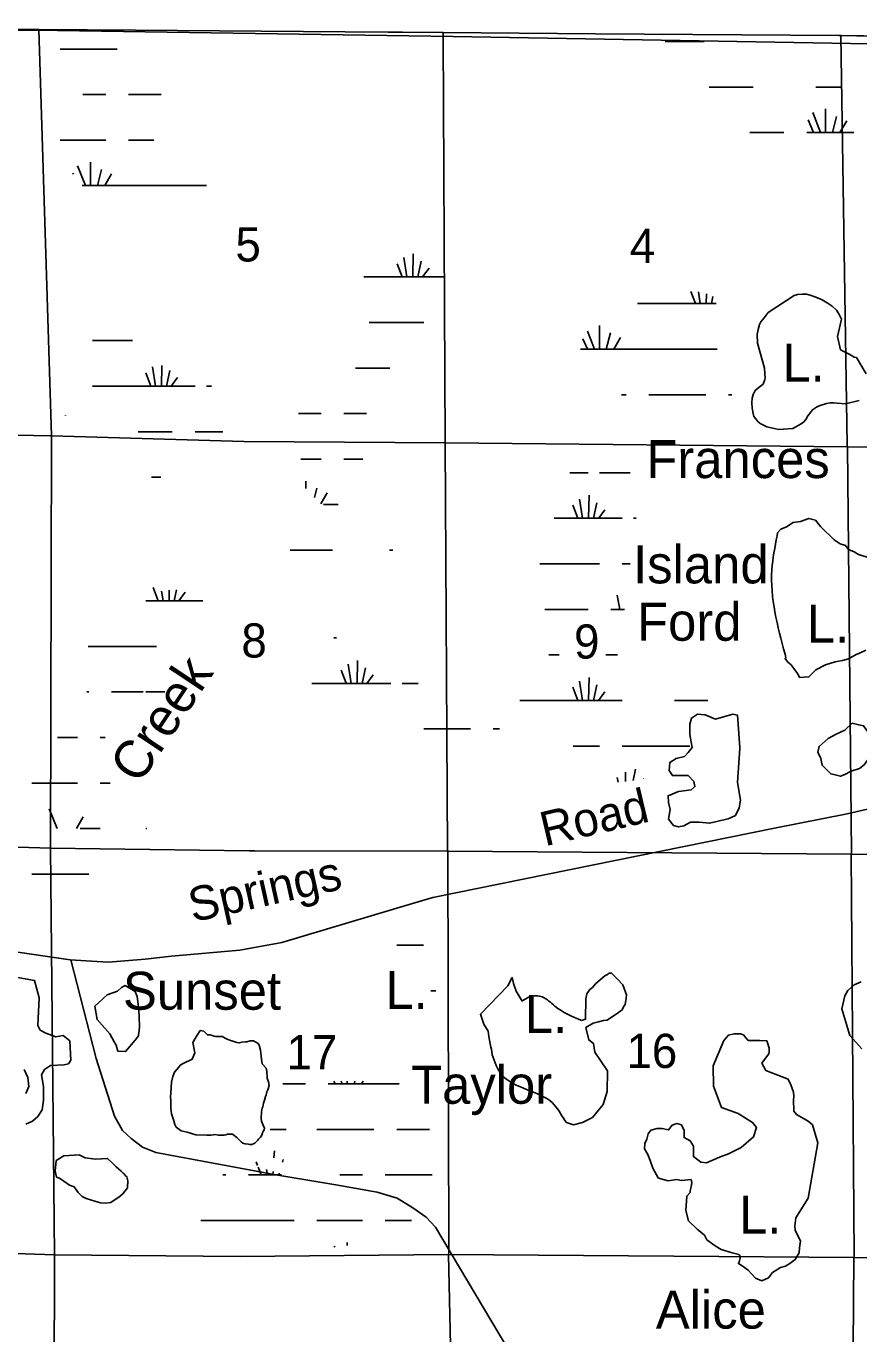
# Model space of a CAD drawing. Extents: x 380424 to 701066, y 1117407 to 1412949.
# Drawn here: x 451978 to 462944, y 1379088 to 1396314 of the extents above; entities that cross this region are included whole.
import ezdxf

# ---------------------------------------------------------------- set-up
doc = ezdxf.new("R2010")
doc.units = 0
for name, color, linetype in [('County Boundary', 7, 'Continuous'), ('Lakes and Ponds', 7, 'Continuous'), ('Lakes and Ponds Text', 7, 'Continuous'), ('Local Roads Paved', 7, 'Continuous'), ('Local Roads Related Text', 7, 'Continuous'), ('Narrow River Creek and Branch and Slough Text', 7, 'Continuous'), ('Section Lines', 7, 'Continuous'), ('Section Numbers', 7, 'Continuous'), ('Swamps', 7, 'Continuous'), ('Township  and Range lines', 7, 'Continuous')]:
    doc.layers.add(name, color=color, linetype=linetype)

msp = doc.modelspace()

# ---------------------------------------------------------------- linework, layer by layer
at = {"layer": 'County Boundary'}
msp.add_lwpolyline([(444709, 1396293), (446440, 1396285), (452102, 1396261), (457598, 1396176), (465384, 1396044), (465655, 1396044), (481571, 1395878), (501713, 1395620), (510342, 1395422), (515666, 1395275), (520926, 1395193), (525511, 1395188), (531177, 1395181), (531365, 1395181), (536977, 1395158), (542179, 1395155), (542521, 1395155), (587352, 1395146), (594829, 1395183), (611544, 1395147), (638076, 1395204)], dxfattribs=at)
at = {"layer": 'Lakes and Ponds'}
for points in [[(462946, 1391384), (462766, 1391337), (462659, 1391348), (462613, 1391354), (462566, 1391352), (462519, 1391344), (462422, 1391314), (462388, 1391297), (462335, 1391259), (462305, 1391223), (462271, 1391180), (462244, 1391131), (462214, 1391097), (462186, 1391076), (462076, 1391015), (461891, 1391000), (461734, 1391034), (461645, 1391078), (461615, 1391106), (461586, 1391140), (461560, 1391174), (461550, 1391210), (461537, 1391280), (461535, 1391354), (461539, 1391414), (461550, 1391464), (461579, 1391513), (461632, 1391560), (461683, 1391600), (461705, 1391658), (461709, 1391675), (461707, 1391738), (461702, 1391806), (461700, 1391810), (461611, 1392139), (461607, 1392177), (461603, 1392218), (461603, 1392252), (461618, 1392317), (461637, 1392383), (461652, 1392419), (461696, 1392474), (461749, 1392542), (462093, 1392765), (462137, 1392778), (462197, 1392784), (462254, 1392782), (462301, 1392769), (462377, 1392744), (462460, 1392710), (462526, 1392670), (462594, 1392625), (462649, 1392574), (462679, 1392523), (462715, 1392455), (462664, 1392227), (462703, 1392052), (462825, 1391988), (462884, 1391955), (462912, 1391948), (463041, 1391732)], [(463187, 1389279), (462941, 1389355), (462882, 1389390), (462809, 1389418), (462768, 1389474), (462699, 1389495), (462617, 1389546), (462440, 1389722), (462371, 1389807), (462286, 1389830), (462175, 1389791), (462079, 1389775), (461990, 1389717), (461916, 1389686), (461874, 1389638), (461868, 1389602)], [(461972, 1388042), (461982, 1387994), (461973, 1387985), (462010, 1387936), (462052, 1387902), (462110, 1387824), (462138, 1387784), (462164, 1387736), (462286, 1387741), (462375, 1387837), (462504, 1387899), (462631, 1387939), (462729, 1387959), (462808, 1387980), (462919, 1388043), (462935, 1388048), (463035, 1388094)], [(451975, 1381851), (452062, 1381890), (452133, 1381953), (452188, 1382040), (452204, 1382166), (452204, 1382348), (452180, 1382498), (452220, 1382569), (452298, 1382624), (452480, 1382632), (452535, 1382647), (452566, 1382695), (452551, 1382947), (452464, 1383018), (452369, 1383002), (452235, 1383050), (452164, 1383089), (452133, 1383152), (452149, 1383515), (452086, 1383744), (451299, 1383885)], [(458115, 1382765), (458106, 1382838), (458097, 1382865), (458087, 1382910), (458072, 1383007), (458061, 1383076), (458006, 1383168), (457961, 1383299), (458320, 1383674), (458362, 1383745), (458370, 1383773), (458378, 1383784), (458394, 1383704), (458431, 1383603), (458510, 1383471)], [(459289, 1383218), (459345, 1383232), (459350, 1383503), (459361, 1383565), (459403, 1383623), (459435, 1383650), (459477, 1383697), (459572, 1383782), (459599, 1383803), (459635, 1383824), (459657, 1383840), (459688, 1383840), (459766, 1383761), (459834, 1383684), (459885, 1383556), (459879, 1383509), (459865, 1383426), (459846, 1383395), (459825, 1383358), (459761, 1383308), (459671, 1383250), (459629, 1383222), (459580, 1383218), (459517, 1383200), (459445, 1383182), (459350, 1383123), (459386, 1382960), (459449, 1382915), (459467, 1382797), (459635, 1382553), (459630, 1382281), (459576, 1382109), (459436, 1381937), (459304, 1381874), (459187, 1381842), (459092, 1381874), (459070, 1381898)], [(462981, 1382844), (462827, 1383019), (462719, 1383368), (462759, 1383543), (462800, 1383610), (462880, 1383684), (462974, 1383724)], [(451951, 1382569), (451999, 1382466), (452015, 1382348), (451975, 1382253)]]:
    msp.add_lwpolyline(points, dxfattribs=at)
for points in [[(461375, 1386803), (461347, 1386349), (461383, 1386118), (461368, 1386017), (461318, 1385916), (461224, 1385873), (460979, 1385815), (460842, 1385830), (460727, 1385830), (460640, 1385779), (460568, 1385765), (460503, 1385786), (460438, 1385866), (460460, 1385996), (460438, 1386089), (460431, 1386176), (460568, 1386234), (460734, 1386255), (460784, 1386298), (460770, 1386363), (460698, 1386443), (460489, 1386443), (460446, 1386508), (460453, 1386616), (460539, 1386666), (460647, 1386695), (460698, 1386745), (460748, 1386810), (460720, 1386983), (460720, 1387120), (460741, 1387200), (460820, 1387250), (460921, 1387243), (461058, 1387185), (461282, 1387250), (461347, 1387236), (461375, 1386810)], [(463128, 1386874), (463133, 1386926), (463073, 1387001), (463006, 1387099), (462942, 1387109), (462855, 1387131), (462760, 1387042), (462643, 1386988), (462541, 1386931), (462421, 1386827), (462405, 1386752), (462443, 1386665), (462460, 1386579), (462507, 1386532), (462573, 1386463), (462630, 1386450), (462700, 1386434), (462760, 1386457), (462843, 1386499), (462954, 1386536), (463012, 1386583), (463059, 1386647), (463117, 1386752)], [(453462, 1383360), (453441, 1383534), (453411, 1383597), (453282, 1383675), (453232, 1383652), (453179, 1383601), (453045, 1383553), (452882, 1383403), (452912, 1383228), (453079, 1383039), (453105, 1382991), (453133, 1382945), (453165, 1382892), (453183, 1382812), (453287, 1382807), (453413, 1382957), (453455, 1383014), (453455, 1383033), (453466, 1383077), (453469, 1383146), (453466, 1383251)], [(454670, 1382954), (454617, 1382974), (454560, 1383004), (454522, 1383004), (454502, 1383004), (454473, 1383006), (454453, 1383009), (454401, 1383025), (454364, 1383026), (454317, 1383076), (454270, 1383083), (454228, 1383024), (454173, 1382925), (454198, 1382791), (454164, 1382706), (454045, 1382651), (454008, 1382628), (453988, 1382603), (453932, 1382534), (453909, 1382477), (453891, 1382405), (453887, 1382338), (453884, 1382254), (453879, 1382212), (453882, 1382163), (453884, 1382113), (453882, 1382061), (453891, 1381985), (453906, 1381945), (453921, 1381896), (453936, 1381844), (453953, 1381811), (454020, 1381764), (454100, 1381744), (454210, 1381712), (454359, 1381705), (454413, 1381705), (454468, 1381713), (454508, 1381705), (454584, 1381705), (454609, 1381712), (454631, 1381719), (454693, 1381717), (454752, 1381675), (454807, 1381618), (454829, 1381601), (454862, 1381593), (454905, 1381586), (454923, 1381581), (454950, 1381584), (454990, 1381599), (455027, 1381641), (455039, 1381651), (455064, 1381680), (455081, 1381707), (455092, 1381737), (455098, 1381754), (455113, 1381774), (455118, 1381799), (455096, 1381844), (455076, 1381891), (455071, 1381930), (455071, 1381962), (455077, 1381988), (455077, 1382015), (455084, 1382060), (455094, 1382080), (455104, 1382128), (455118, 1382165), (455130, 1382213), (455133, 1382222), (455138, 1382237), (455143, 1382254), (455145, 1382276), (455160, 1382301), (455178, 1382359), (455170, 1382410), (455150, 1382455), (455150, 1382465), (455145, 1382544), (455138, 1382587), (455086, 1382645), (455079, 1382707), (455064, 1382826), (455048, 1382891), (455033, 1382911), (454970, 1382949), (454928, 1382947), (454882, 1382933), (454865, 1382935), (454820, 1382930), (454783, 1382920), (454750, 1382927), (454714, 1382938), (454685, 1382948)], [(462086, 1382020), (462084, 1382171), (462087, 1382215), (462082, 1382273), (462048, 1382369), (462015, 1382445), (461718, 1382557), (461668, 1382654), (461754, 1382771), (461764, 1382790), (461764, 1382852), (461743, 1382910), (461732, 1382947), (461634, 1382953), (461637, 1382953), (461485, 1382953), (461454, 1382989), (461429, 1383024), (461388, 1383039), (461353, 1383039), (461302, 1383039), (461226, 1383024), (461165, 1382953), (461023, 1382618), (461028, 1382349), (461134, 1382069), (461353, 1381993), (461544, 1381874), (461595, 1381808), (461556, 1381683), (461393, 1381541), (461226, 1381460), (461109, 1381414), (460936, 1381343), (460863, 1381351), (460764, 1381424), (460764, 1381561), (460723, 1381632), (460642, 1381673), (460642, 1381765), (460606, 1381841), (460545, 1381861), (460484, 1381836), (460439, 1381775), (460352, 1381795), (460288, 1381795), (460205, 1381770), (460169, 1381724), (460152, 1381652), (460124, 1381597), (460119, 1381526), (460164, 1381450), (460196, 1381372), (460229, 1381271), (460300, 1381142), (460337, 1381132), (460431, 1381103), (460544, 1381120), (460606, 1381109), (460734, 1381120), (460745, 1381083), (460739, 1381052), (460729, 1381009), (460723, 1380972), (460723, 1380951), (460677, 1380902), (460666, 1380711), (460700, 1380576), (460814, 1380469), (460911, 1380386), (460943, 1380328), (461053, 1380246), (461129, 1380200), (461277, 1380154), (461363, 1380134), (461385, 1380106), (461370, 1380050), (461358, 1380014), (461405, 1379984), (461486, 1379927), (461582, 1379820), (461667, 1379785), (461753, 1379824), (461806, 1379895), (461913, 1379963), (461979, 1379982), (462033, 1380016), (462104, 1380068), (462157, 1380154), (462162, 1380223), (462175, 1380312), (462104, 1380449), (462102, 1380513), (462112, 1380618), (462277, 1380876), (462405, 1381603), (462333, 1381841), (462277, 1381892), (462191, 1381937), (462123, 1381977)], [(452891, 1381391), (453050, 1381400), (453118, 1381332), (453161, 1381288), (453200, 1381256), (453227, 1381231), (453257, 1381206), (453271, 1381191), (453283, 1381174), (453302, 1381157), (453317, 1381106), (453313, 1381011), (453249, 1380933), (453200, 1380890), (453152, 1380856), (453092, 1380819), (453028, 1380809), (452955, 1380812), (452882, 1380834), (452768, 1380870), (452715, 1380897), (452662, 1380948), (452611, 1381026), (452550, 1381045), (452472, 1381098), (452416, 1381140), (452378, 1381154), (452368, 1381191), (452358, 1381234), (452375, 1381370), (452475, 1381431), (452676, 1381446), (452754, 1381409)]]:
    msp.add_lwpolyline(points, close=True, dxfattribs=at)
for points in [[(461868, 1389602), (461798, 1389153), (461972, 1388042)], [(458510, 1383471), (458608, 1383526), (458775, 1383526), (458941, 1383404), (459289, 1383218)], [(459070, 1381898), (458908, 1382130), (458243, 1382499), (458115, 1382765)]]:
    msp.add_spline(points, degree=3, dxfattribs=at)
at = {"layer": 'Local Roads Paved'}
for points in [[(469461, 1387536), (466024, 1387550), (465889, 1387546), (465789, 1387515), (465684, 1387465), (465349, 1387171), (464894, 1386801), (464508, 1386558), (464145, 1386328), (463823, 1386194), (463609, 1386127), (462790, 1385939), (461833, 1385748), (457335, 1384838), (457067, 1384758), (455344, 1384242), (454790, 1384144), (453892, 1384064), (453543, 1384023), (453060, 1383983), (452838, 1383997), (452557, 1384017), (451087, 1384231)], [(452565, 1384016), (452899, 1382714), (453140, 1381956), (453247, 1381768), (453362, 1381660), (453509, 1381546), (453684, 1381479), (455294, 1381178), (456058, 1381050), (456602, 1380956), (456863, 1380876), (457071, 1380748), (457246, 1380627), (457367, 1380493), (458316, 1378899)]]:
    msp.add_lwpolyline(points, dxfattribs=at)
at = {"layer": 'Section Lines'}
for points in [[(452145, 1396270), (452145, 1396270), (452310, 1390916), (452298, 1390916), (446467, 1391031), (446457, 1391031), (446390, 1394947), (446378, 1395736), (446371, 1396147), (446364, 1396314), (446370, 1396314), (446372, 1396314), (446837, 1396310), (452144, 1396270)], [(457468, 1396229), (457468, 1396229), (457468, 1396163), (457497, 1390841), (457495, 1390825), (454844, 1390842), (452310, 1390916), (452145, 1396270), (452145, 1396270), (453416, 1396260), (453416, 1396260), (456177, 1396239), (456179, 1396239), (456744, 1396234), (456936, 1396233), (457452, 1396229), (457452, 1396229)], [(462708, 1396189), (462788, 1390793), (462795, 1390773), (457495, 1390825), (457497, 1390841), (457468, 1396163), (457468, 1396229), (457468, 1396229), (459476, 1396214), (462681, 1396189)], [(467981, 1396111), (467981, 1396111), (468137, 1390729), (462795, 1390773), (462788, 1390793), (462708, 1396189), (462711, 1396189), (464812, 1396158), (464993, 1396155), (466037, 1396140), (467582, 1396117)], [(452310, 1390916), (452299, 1385488), (446615, 1385661), (446601, 1385661), (446601, 1385678), (446495, 1389346), (446475, 1390128), (446467, 1390421), (446460, 1390858), (446457, 1391031), (446467, 1391031), (452298, 1390916)], [(457495, 1390825), (457526, 1385461), (457529, 1385445), (454991, 1385449), (454915, 1385450), (452299, 1385488), (452310, 1390916), (454844, 1390842)], [(462795, 1390773), (462847, 1385421), (462842, 1385405), (457529, 1385445), (457526, 1385461), (457495, 1390825)], [(468137, 1390729), (468136, 1385356), (462842, 1385405), (462847, 1385421), (462795, 1390773)], [(452299, 1385488), (452350, 1380129), (446680, 1380322), (446680, 1380322), (446680, 1380323), (446680, 1380324), (446601, 1385661), (446615, 1385661)], [(457529, 1385445), (457546, 1380158), (457541, 1380133), (454794, 1380109), (452350, 1380129), (452299, 1385488), (454915, 1385450), (454991, 1385449)], [(462842, 1385405), (462880, 1380113), (462877, 1380092), (457541, 1380133), (457546, 1380158), (457529, 1385445)], [(468136, 1385356), (468132, 1380031), (468135, 1380016), (462877, 1380092), (462880, 1380113), (462842, 1385405)], [(452350, 1380129), (452338, 1374951), (446760, 1374945), (446760, 1374945), (446680, 1380322), (446680, 1380322)], [(457541, 1380133), (457653, 1374938), (454750, 1374954), (452338, 1374951), (452350, 1380129), (454794, 1380109)], [(462877, 1380092), (462839, 1374767), (462831, 1374772), (457653, 1374938), (457541, 1380133)], [(468135, 1380016), (468109, 1374719), (462839, 1374767), (462877, 1380092)]]:
    msp.add_lwpolyline(points, close=True, dxfattribs=at)
at = {"layer": 'Swamps'}
for p, q in [((452425, 1396013), (453175, 1396013)), ((452725, 1395413), (453025, 1395413)), ((462337, 1395175), (462440, 1394912)), ((462506, 1395223), (462506, 1394912)), ((462651, 1395126), (462597, 1394912)), ((462276, 1395078), (462347, 1394912)), ((462784, 1395066), (462694, 1394912)), ((452425, 1394813), (453025, 1394813)), ((453325, 1394813), (453660, 1394813)), ((461507, 1394912), (461957, 1394912)), ((452824, 1394524), (452824, 1394213)), ((452969, 1394427), (452915, 1394213)), ((453102, 1394367), (453012, 1394213)), ((456991, 1393011), (456952, 1393265)), ((457069, 1393011), (457075, 1393315)), ((457137, 1393011), (457179, 1393217)), ((456929, 1393012), (456863, 1393185)), ((457199, 1393011), (457283, 1393124)), ((460028, 1392659), (460628, 1392659)), ((456763, 1392411), (457213, 1392411)), ((459527, 1392370), (459527, 1392059)), ((459672, 1392273), (459618, 1392059)), ((459805, 1392213), (459715, 1392059)), ((460628, 1392059), (461078, 1392059)), ((453618, 1391573), (453552, 1391746)), ((453680, 1391572), (453641, 1391825)), ((453825, 1391572), (453868, 1391778)), ((453887, 1391571), (453971, 1391685)), ((456313, 1391811), (456763, 1391811)), ((452852, 1391572), (453452, 1391572)), ((453452, 1391572), (454202, 1391572)), ((460178, 1391459), (460628, 1391459)), ((460628, 1391459), (460928, 1391459)), ((455563, 1391211), (455863, 1391211)), ((453452, 1390972), (453902, 1390972)), ((455807, 1390226), (455777, 1390106)), ((455940, 1390165), (455857, 1390023)), ((459384, 1389831), (459390, 1390134)), ((459244, 1389832), (459178, 1390005)), ((459306, 1389831), (459267, 1390084)), ((459451, 1389831), (459494, 1390036)), ((459514, 1389830), (459597, 1389944)), ((459078, 1389831), (459828, 1389831)), ((455455, 1389411), (456013, 1389411)), ((459078, 1389231), (459528, 1389231)), ((453718, 1388745), (453652, 1388918)), ((453553, 1388744), (454303, 1388744)), ((453781, 1388744), (453761, 1388871)), ((453859, 1388744), (453861, 1388884)), ((453926, 1388744), (453957, 1388891)), ((453988, 1388743), (454072, 1388857)), ((459760, 1388817), (459798, 1388631)), ((459078, 1388631), (459378, 1388631)), ((453553, 1388144), (453692, 1388144)), ((456257, 1387657), (456217, 1387910)), ((456335, 1387657), (456340, 1387960)), ((456194, 1387658), (456128, 1387831)), ((456402, 1387657), (456445, 1387862)), ((456464, 1387656), (456548, 1387770)), ((459384, 1387431), (459390, 1387734)), ((453103, 1387544), (453519, 1387544)), ((455739, 1387657), (456029, 1387657)), ((456029, 1387657), (456779, 1387657)), ((459244, 1387432), (459178, 1387605)), ((459306, 1387431), (459267, 1387684)), ((459451, 1387431), (459494, 1387636)), ((459514, 1387430), (459597, 1387544)), ((458478, 1387431), (459078, 1387431)), ((459078, 1387431), (459828, 1387431)), ((452053, 1386344), (452653, 1386344)), ((452282, 1386006), (452385, 1385744)), ((452729, 1385898), (452639, 1385744)), ((452690, 1385744), (452954, 1385744)), ((452053, 1385144), (452803, 1385144)), ((456031, 1382417), (456047, 1382381)), ((456125, 1382417), (456139, 1382381)), ((456205, 1382417), (456205, 1382381)), ((456306, 1382417), (456297, 1382381)), ((456414, 1382417), (456394, 1382381)), ((455807, 1381781), (456557, 1381781)), ((455025, 1381304), (455007, 1381353)), ((455241, 1381405), (455246, 1381497)), ((455354, 1381351), (455363, 1381385)), ((454907, 1381181), (455340, 1381181)), ((455072, 1381181), (455033, 1381285)), ((455157, 1381181), (455144, 1381252)), ((455228, 1381181), (455231, 1381227)), ((455305, 1381181), (455311, 1381203)), ((455382, 1381181), (455382, 1381182)), ((456107, 1381181), (456407, 1381181)), ((456707, 1381181), (457307, 1381181)), ((455807, 1380581), (456407, 1380581))]:
    msp.add_line(p, q, dxfattribs=at)
for points in [[(460392, 1396112), (460907, 1396112)], [(460971, 1395512), (461552, 1395512)], [(462375, 1395512), (462707, 1395512)], [(453325, 1395413), (453755, 1395413)], [(462257, 1394912), (462877, 1394912)], [(452655, 1394475), (452758, 1394213)], [(452594, 1394379), (452601, 1394364)], [(452714, 1394213), (453925, 1394213)], [(453925, 1394213), (454354, 1394213)], [(456423, 1393011), (456763, 1393011)], [(456763, 1393011), (457488, 1393011)], [(460794, 1392660), (460733, 1392819)], [(460856, 1392659), (460832, 1392816)], [(460934, 1392659), (460937, 1392786)], [(461001, 1392659), (461021, 1392751)], [(460628, 1392659), (461063, 1392659)], [(456493, 1392411), (456763, 1392411)], [(459310, 1392195), (459368, 1392059)], [(459368, 1392295), (459461, 1392059)], [(452852, 1392172), (453376, 1392172)], [(459280, 1392059), (460628, 1392059)], [(453758, 1391572), (453763, 1391845)], [(456763, 1391811), (456768, 1391811)], [(454352, 1391572), (454420, 1391572)], [(459820, 1391459), (459878, 1391459)], [(461228, 1391459), (461272, 1391459)], [(452496, 1391186), (452494, 1391179)], [(456163, 1391211), (456458, 1391211)], [(454202, 1390972), (454568, 1390972)], [(455597, 1390611), (455863, 1390611)], [(456163, 1390611), (456410, 1390611)], [(453628, 1390372), (453752, 1390372)], [(455662, 1390322), (455662, 1390222)], [(459139, 1390431), (459378, 1390431)], [(459528, 1390431), (459932, 1390431)], [(455892, 1390011), (456085, 1390011)], [(458930, 1389831), (459078, 1389831)], [(459978, 1389831), (460012, 1389831)], [(456763, 1389411), (456806, 1389411)], [(458743, 1389231), (459078, 1389231)], [(459828, 1389231), (459932, 1389231)], [(458808, 1388631), (459078, 1388631)], [(459678, 1388631), (459859, 1388631)], [(456029, 1388257), (456065, 1388257)], [(452793, 1388144), (453553, 1388144)], [(458861, 1388031), (458999, 1388031)], [(459611, 1388031), (459764, 1388031)], [(452775, 1387544), (452803, 1387544)], [(453553, 1387544), (453802, 1387544)], [(456929, 1387657), (457142, 1387657)], [(460515, 1387431), (460955, 1387431)], [(457213, 1387057), (457829, 1387057)], [(458129, 1387057), (458213, 1387057)], [(452392, 1386944), (452653, 1386944)], [(452953, 1386944), (453017, 1386944)], [(459180, 1386831), (459528, 1386831)], [(459828, 1386831), (460716, 1386831)], [(460002, 1386526), (459972, 1386377)], [(452953, 1386344), (453085, 1386344)], [(459760, 1386417), (459773, 1386356)], [(459869, 1386489), (459869, 1386363)], [(460111, 1386405), (460109, 1386401)], [(453553, 1385744), (453568, 1385744)], [(456857, 1384207), (457210, 1384207)], [(457307, 1383607), (457374, 1383607)], [(455360, 1382381), (455657, 1382381)], [(455957, 1382381), (456889, 1382381)], [(455191, 1381781), (455402, 1381781)], [(456857, 1381781), (457289, 1381781)], [(454569, 1381181), (454607, 1381181)], [(457307, 1381181), (457325, 1381181)], [(454276, 1380581), (455507, 1380581)], [(456707, 1380581), (457051, 1380581)], [(456036, 1380244), (456043, 1380228)], [(456205, 1380292), (456205, 1380254)]]:
    msp.add_lwpolyline(points, dxfattribs=at)
at = {"layer": 'Township  and Range lines'}
for p, q in [((446837, 1396310), (452144, 1396270)), ((452144, 1396270), (452145, 1396270)), ((452145, 1396270), (453416, 1396260)), ((453416, 1396260), (456177, 1396239)), ((456177, 1396239), (456179, 1396239)), ((456179, 1396239), (456744, 1396234)), ((456744, 1396234), (456936, 1396233)), ((456936, 1396233), (457452, 1396229)), ((457452, 1396229), (457468, 1396229)), ((457468, 1396229), (459476, 1396214)), ((459476, 1396214), (462681, 1396189)), ((462681, 1396189), (462708, 1396189)), ((462708, 1396189), (462711, 1396189)), ((462711, 1396189), (464812, 1396158))]:
    msp.add_line(p, q, dxfattribs=at)

# ---------------------------------------------------------------- texts
at = {"layer": 'Lakes and Ponds Text'}
for s, rotation, p in [('L.', 0, (461937, 1391631)), ('Frances', 0, (460145, 1390361)), ('Island', 0, (459971, 1388974)), ('Ford', 0, (460023, 1388218)), ('L.', 0, (462259, 1388193)), ('Sunset', 0, (453253, 1383358)), ('L.', 0, (456709, 1383369)), ('L.', 0, (458546, 1383053)), ('Taylor', 0, (457047, 1382119)), ('L.', 0.0001, (461366, 1380408)), ('Alice', 0.0001, (460270, 1379157))]:
    msp.add_text(s, height=500, rotation=rotation, dxfattribs=at).set_placement(p)
at = {"layer": 'Local Roads Related Text'}
for s, rotation, p in [('Road', 13.3318, (458808, 1385509)), ('Springs', 12.5356, (454171, 1384509))]:
    msp.add_text(s, height=450, rotation=rotation, dxfattribs=at).set_placement(p)
at = {"layer": 'Narrow River Creek and Branch and Slough Text'}
msp.add_text('Creek', height=500, rotation=56.3547, dxfattribs=at).set_placement((453467, 1386311))
at = {"layer": 'Section Numbers'}
for s, p in [('5', (454734, 1393214)), ('4', (459927, 1393196)), ('8', (454812, 1387997)), ('9', (459193, 1387983)), ('17', (455406, 1382573)), ('16', (459883, 1382591))]:
    msp.add_text(s, height=450, dxfattribs=at).set_placement(p)

doc.saveas('drawing.dxf')
